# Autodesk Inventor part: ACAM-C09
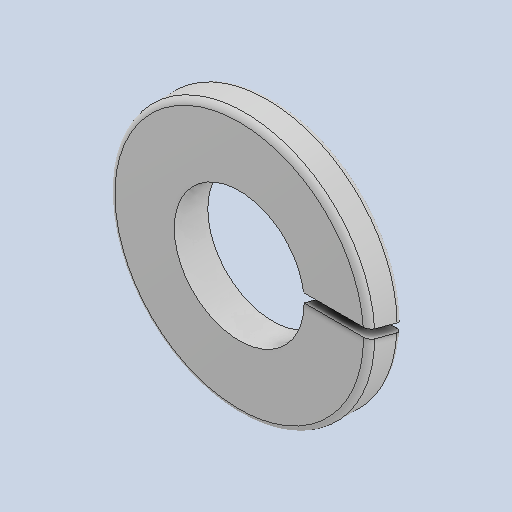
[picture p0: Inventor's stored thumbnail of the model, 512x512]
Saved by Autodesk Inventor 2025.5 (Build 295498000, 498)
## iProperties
Created: 2026-10
Part Number: ACAM-C09
Material: Genérico
Document SubType Name: Modeling
Designer: Luis M
Density: 1 g/cm^3
Appearance: Valor por defecto
Description: Arandela de presión M3 — DIN 127 B
Sending System: SolidEdge
MC: COSTA-PC
OS: Windows NT
OS_RELEASE: 6.1
FRU: Unigraphics Solutions
SITE: Huntsville, AL
FORMAT: text
GUISE: transmit
KEY: D:\Videos_Canal\GrabCAD\Arruela de pressao DIN 127 B\Arruela de pressao DIN 127 B - M3
FILE: D:\Videos_Canal\GrabCAD\Arruela de pressao DIN 127 B\Arruela de pressao DIN 127 B - M3.x_t
DATE: ter, abr 05 16
Material_BOM: Por especificar
Proceso_BOM: Comercial
Author: Luis M
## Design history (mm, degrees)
feature "Base1"
node "Sólido1"
